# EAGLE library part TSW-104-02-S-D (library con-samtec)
THROUGH-HOLE .025" SQ POST HEADER Source: Samtec TSW.pdf
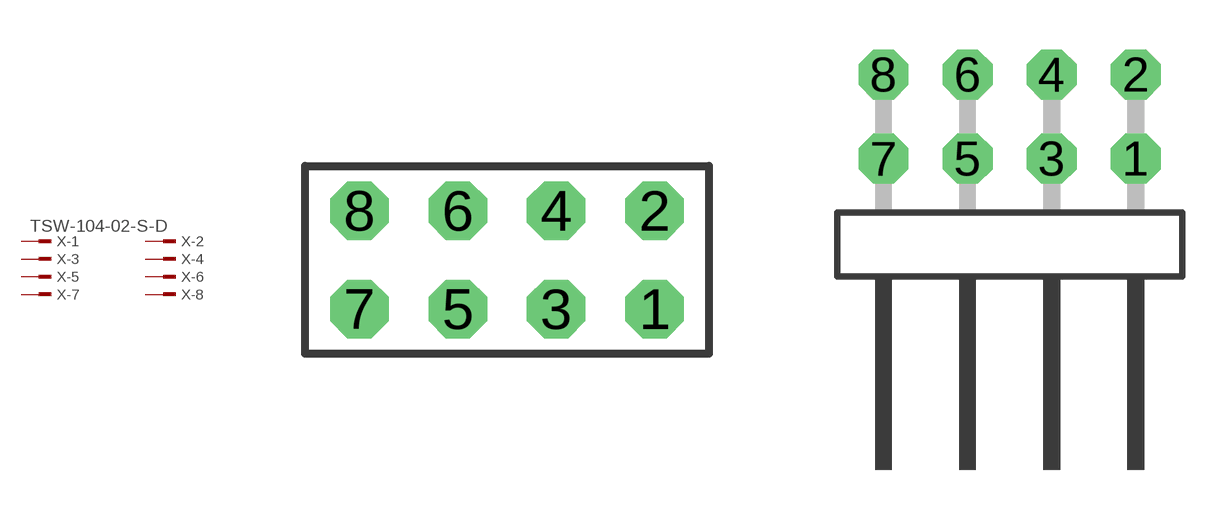
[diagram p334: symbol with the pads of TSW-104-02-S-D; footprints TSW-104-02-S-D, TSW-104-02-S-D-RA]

Designator prefix X; gates -1=MPINV -2=MPIN -3=MPIN -4=MPIN -5=MPIN -6=MPIN -7=MPIN -8=MPIN

## TSW-104-02-S-D (OC_FARNELL: unknown; OC_NEWARK: unknown)  [TSW-104-02-S-D]
1  -1:1  pas
2  -2:1  pas
3  -3:1  pas
4  -4:1  pas
5  -5:1  pas
6  -6:1  pas
7  -7:1  pas
8  -8:1  pas

## TSW-104-02-S-D-RA (OC_FARNELL: unknown; OC_NEWARK: unknown)  [TSW-104-02-S-D-RA]
Pads as for TSW-104-02-S-D

## Footprint TSW-104-02-S-D (pad centres in mm)
THROUGH-HOLE .025" SQ POST HEADER Source: Samtec TSW.pdf
drill 1 pad 1.5 octagon: 1 3.81,-1.27; 2 3.81,1.27; 3 1.27,-1.27; 4 1.27,1.27; 5 -1.27,-1.27; 6 -1.27,1.27; 7 -3.81,-1.27; 8 -3.81,1.27

## Footprint TSW-104-02-S-D-RA (pad centres in mm)
THROUGH-HOLE .025" SQ POST HEADER Source: Samtec TSW.pdf
drill 1 pad 1.5 octagon: 1 3.81,1.524; 2 3.81,4.064; 3 1.27,1.524; 4 1.27,4.064; 5 -1.27,1.524; 6 -1.27,4.064; 7 -3.81,1.524; 8 -3.81,4.064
